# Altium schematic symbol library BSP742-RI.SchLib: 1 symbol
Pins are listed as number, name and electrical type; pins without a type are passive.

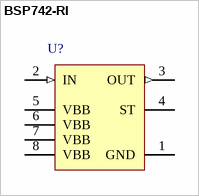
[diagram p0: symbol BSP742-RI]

## BSP742-RI
designator U?
Smart High-Side-Switch, 1 Channel, 1.2 A Load Current, -40 to 150 degC, PG-DSO-8-24, Reel, Green; Manufacturer: Infineon; PartNumber: BSP742-RI; Channels: 1; Green: TRUE; Group: Automotive Qualified; Load Current (typ): 1.1 A; Ptot (max): 1.5 W; Recommended Operating Voltage Max.: 34 V; Recommended Operating Voltage Min.: 5 V; RON @ 25degreesC: 350 mOhm; RON(max) @ 150degreesC: 700 mOhm; toff (max): 170 us; ton (max): 140 us
footprint INF-PG-DSO-8-24_N (SOP, 8-Leads, Body 4.9x3.9mm, Pitch 1.27mm, IPC Medium Density)
footprint INF-PG-DSO-8-24_L (SOP, 8-Leads, Body 4.9x3.9mm, Pitch 1.27mm, IPC High Density)
footprint INF-PG-DSO-8-24_M (SOP, 8-Leads, Body 4.9x3.9mm, Pitch 1.27mm, IPC Low Density)
pins: 1 GND (power) "Logic ground", 2 IN (in) "Input, activates the power switch in case of logic high signal", 3 OUT (out) "Output to the load", 4 ST (oc) "Diagnostic feedback", 5 VBB (power) "Positive power supply voltage", 6 VBB (power) "Positive power supply voltage", 7 VBB (power) "Positive power supply voltage", 8 VBB (power) "Positive power supply voltage"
